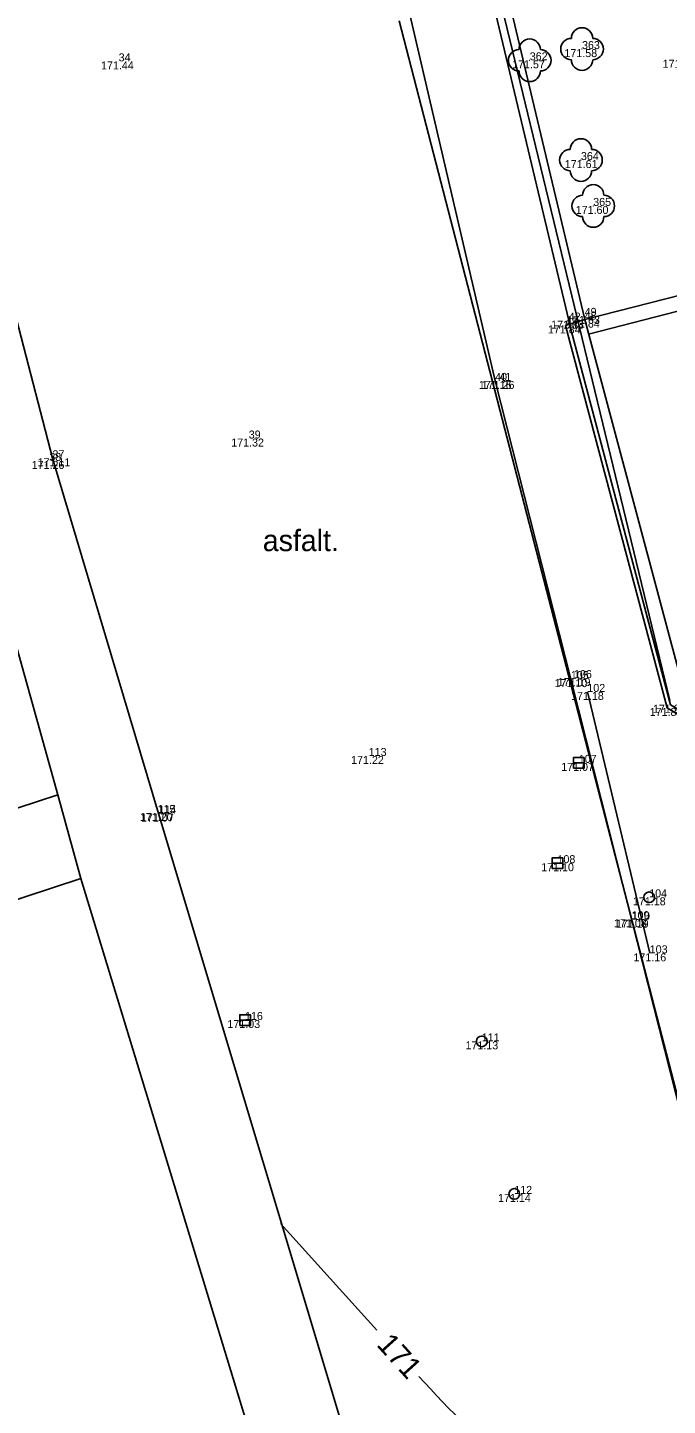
# Model space of a CAD drawing. Extents: x -749392 to -748966, y -963885 to -963538.
# Drawn here: x -749236.19 to -749224.19, y -963704.92 to -963679.09 of the extents above; entities that cross this region are included whole.
import ezdxf

# ---------------------------------------------------------------- set-up
doc = ezdxf.new("R2010")
doc.units = 0
for name, color, linetype in [('_Body výšky', 7, 'Continuous'), ('_Body čísla', 7, 'Continuous'), ('_KM hranice parcel', 7, 'Continuous'), ('_KM vnitřní kresba', 7, 'Continuous'), ('_Kresba', 7, 'Continuous'), ('Vrstevnice', 7, 'Continuous')]:
    doc.layers.add(name, color=color, linetype=linetype)

msp = doc.modelspace()

# ---------------------------------------------------------------- linework, layer by layer
at = {"layer": '_Body čísla'}
for p, q in [((-749225.79, -963679.49), (-749225.79, -963679.49)), ((-749234.48, -963679.72), (-749234.48, -963679.72)), ((-749226.77, -963679.7), (-749226.77, -963679.7)), ((-749225.81, -963681.57), (-749225.81, -963681.57)), ((-749225.58, -963682.43), (-749225.58, -963682.43)), ((-749225.74, -963684.49), (-749225.74, -963684.49)), ((-749226.1, -963684.67), (-749226.1, -963684.67)), ((-749226.04, -963684.58), (-749226.04, -963684.58)), ((-749225.74, -963684.56), (-749225.74, -963684.56)), ((-749227.42, -963685.71), (-749227.42, -963685.71)), ((-749227.34, -963685.71), (-749227.34, -963685.71)), ((-749232.04, -963686.79), (-749232.04, -963686.79)), ((-749235.78, -963687.21), (-749235.78, -963687.21)), ((-749235.72, -963687.16), (-749235.72, -963687.16)), ((-749226, -963691.3), (-749226, -963691.3)), ((-749225.94, -963691.28), (-749225.94, -963691.28)), ((-749225.69, -963691.54), (-749225.69, -963691.54)), ((-749224.19, -963691.84), (-749224.19, -963691.84)), ((-749229.79, -963692.74), (-749229.79, -963692.74)), ((-749225.85, -963692.87), (-749225.85, -963692.87)), ((-749233.75, -963693.81), (-749233.75, -963693.81)), ((-749233.73, -963693.82), (-749233.73, -963693.82)), ((-749226.25, -963694.75), (-749226.25, -963694.75)), ((-749224.53, -963695.39), (-749224.53, -963695.39)), ((-749224.86, -963695.8), (-749224.86, -963695.8)), ((-749224.85, -963695.81), (-749224.85, -963695.81)), ((-749224.52, -963696.44), (-749224.52, -963696.44)), ((-749232.11, -963697.69), (-749232.11, -963697.69)), ((-749227.67, -963698.09), (-749227.67, -963698.09)), ((-749227.06, -963700.95), (-749227.06, -963700.95))]:
    msp.add_line(p, q, dxfattribs=at)
at = {"layer": '_KM hranice parcel'}
for p, q in [((-749229.22, -963678.96), (-749222.92, -963703.3)), ((-749238.25, -963684.05), (-749235.62, -963693.47)), ((-749246.57, -963697.02), (-749235.62, -963693.47)), ((-749235.62, -963693.47), (-749235.19, -963695.04)), ((-749231.34, -963707.66), (-749235.19, -963695.04))]:
    msp.add_line(p, q, dxfattribs=at)
at = {"layer": '_KM vnitřní kresba'}
for p, q in [((-749227.34, -963678.51), (-749224.14, -963691.7)), ((-749244.25, -963698.01), (-749235.19, -963695.04))]:
    msp.add_line(p, q, dxfattribs=at)
at = {"layer": '_Kresba'}
for p, q in [((-749225.74, -963684.56), (-749221.1, -963683.37)), ((-749225.67, -963684.834), (-749221.6, -963683.79)), ((-749225.95, -963692.87), (-749225.75, -963692.87)), ((-749226.35, -963694.75), (-749226.15, -963694.75)), ((-749232.21, -963697.69), (-749232.01, -963697.69))]:
    msp.add_line(p, q, dxfattribs=at)
for points in [[(-749224.86, -963695.8), (-749226, -963691.3), (-749227.42, -963685.71), (-749229.02, -963678.84), (-749230.37, -963670.65), (-749232.38, -963656.9), (-749233.81, -963647.95), (-749234.11, -963645.66), (-749234.87, -963640.98), (-749235.33, -963637.99), (-749235.34, -963637.68), (-749233.84, -963637.45), (-749233.66, -963638.02)], [(-749232.344, -963645.034), (-749230.573, -963656.484), (-749228.394, -963670.774), (-749227.175, -963678.512), (-749225.737, -963684.559)], [(-749232.64, -963645.08), (-749230.87, -963656.53), (-749228.69, -963670.82), (-749227.47, -963678.57), (-749226.04, -963684.58)], [(-749241.6, -963658.41), (-749239.69, -963671.39), (-749237.62, -963679.85), (-749235.72, -963687.16), (-749233.73, -963693.82), (-749229.82, -963706.85)], [(-749221.5, -963692.03), (-749222.72, -963692.33), (-749223.86, -963691.58), (-749225.74, -963684.56), (-749226.1, -963684.67), (-749224.19, -963691.84), (-749222.75, -963692.73), (-749221.57, -963692.38), (-749221.26, -963693.64), (-749222.525, -963693.948)], [(-749226.022, -963684.646), (-749226.04, -963684.58)], [(-749222.959, -963692.601), (-749222.97, -963692.47), (-749224.13, -963691.78), (-749226.022, -963684.646)], [(-749224.52, -963696.44), (-749225.69, -963691.54)], [(-749222.67, -963704.44), (-749224.86, -963695.8)]]:
    msp.add_lwpolyline(points, dxfattribs=at)
for points in [[(-749225.95, -963692.97), (-749225.75, -963692.97), (-749225.75, -963692.77), (-749225.95, -963692.77)], [(-749226.35, -963694.85), (-749226.15, -963694.85), (-749226.15, -963694.65), (-749226.35, -963694.65)], [(-749232.21, -963697.79), (-749232.01, -963697.79), (-749232.01, -963697.59), (-749232.21, -963697.59)]]:
    msp.add_lwpolyline(points, close=True, dxfattribs=at)
for centre, radius in [((-749225.79, -963679.49), 0.0002), ((-749226.77, -963679.7), 0.0002), ((-749225.81, -963681.57), 0.0002), ((-749225.58, -963682.43), 0.0002), ((-749224.53, -963695.39), 0.1), ((-749227.67, -963698.09), 0.1), ((-749227.06, -963700.95), 0.1)]:
    msp.add_circle(centre, radius, dxfattribs=at)
for centre, start, end in [((-749225.79, -963679.29), 0, 180), ((-749226.77, -963679.5), 0, 180), ((-749225.99, -963679.49), 90, 270), ((-749225.59, -963679.49), 270, 90), ((-749226.97, -963679.7), 90, 270), ((-749226.57, -963679.7), 270, 90), ((-749226.77, -963679.9), 180, 360), ((-749225.79, -963679.69), 180, 360), ((-749225.81, -963681.37), 0, 180), ((-749226.01, -963681.57), 90, 270), ((-749225.61, -963681.57), 270, 90), ((-749225.81, -963681.77), 180, 360), ((-749225.58, -963682.23), 0, 180), ((-749225.78, -963682.43), 90, 270), ((-749225.38, -963682.43), 270, 90), ((-749225.58, -963682.63), 180, 360)]:
    msp.add_arc(centre, 0.2, start, end, dxfattribs=at)
at = {"layer": 'Vrstevnice'}
msp.add_line((-749231.442, -963701.506), (-749229.64, -963703.501), dxfattribs=at)
msp.add_spline([(-749228.849, -963704.374), (-749226.934, -963706.051), (-749225.717, -963706.552)], degree=3, dxfattribs=at)

# ---------------------------------------------------------------- texts
at = {"layer": '_Body výšky'}
for s, p in [('171.58', (-749226.12, -963679.64)), ('171.44', (-749234.81, -963679.87)), ('171.57', (-749227.1, -963679.85)), ('171.62', (-749224.278, -963679.84)), ('171.61', (-749226.113, -963681.72)), ('171.60', (-749225.908, -963682.58)), ('171.63', (-749226.068, -963684.64)), ('171.84', (-749226.43, -963684.82)), ('171.33', (-749226.368, -963684.73)), ('171.84', (-749226.07, -963684.71)), ('171.16', (-749227.725, -963685.86)), ('171.26', (-749227.67, -963685.86)), ('171.32', (-749232.368, -963686.94)), ('171.26', (-749236.11, -963687.36)), ('171.11', (-749235.999, -963687.31)), ('171.10', (-749226.305, -963691.45)), ('171.19', (-749226.245, -963691.43)), ('171.18', (-749225.995, -963691.69)), ('171.23', (-749224.46, -963691.93)), ('171.85', (-749224.52, -963691.99)), ('171.22', (-749230.12, -963692.89)), ('171.07', (-749226.18, -963693.02)), ('171.20', (-749234.08, -963693.96)), ('171.07', (-749234.06, -963693.97)), ('171.10', (-749226.555, -963694.9)), ('171.18', (-749224.835, -963695.54)), ('171.08', (-749225.19, -963695.95)), ('171.19', (-749225.155, -963695.96)), ('171.16', (-749224.825, -963696.59)), ('171.03', (-749232.44, -963697.84)), ('171.13', (-749227.975, -963698.24)), ('171.14', (-749227.365, -963701.1))]:
    msp.add_text(s, height=0.15, dxfattribs=at).set_placement(p)
at = {"layer": '_Body čísla'}
for s, p in [('363', (-749225.79, -963679.49)), ('34', (-749234.48, -963679.72)), ('362', (-749226.77, -963679.7)), ('364', (-749225.81, -963681.57)), ('365', (-749225.58, -963682.43)), ('43', (-749226.1, -963684.67)), ('42', (-749226.04, -963684.58)), ('49', (-749225.74, -963684.49)), ('48', (-749225.74, -963684.56)), ('40', (-749227.42, -963685.71)), ('41', (-749227.34, -963685.71)), ('39', (-749232.04, -963686.79)), ('38', (-749235.78, -963687.21)), ('37', (-749235.72, -963687.16)), ('105', (-749226, -963691.3)), ('106', (-749225.94, -963691.28)), ('102', (-749225.69, -963691.54)), ('113', (-749229.79, -963692.74)), ('107', (-749225.85, -963692.87)), ('115', (-749233.75, -963693.81)), ('114', (-749233.73, -963693.82)), ('108', (-749226.25, -963694.75)), ('104', (-749224.53, -963695.39)), ('109', (-749224.86, -963695.8)), ('110', (-749224.85, -963695.81)), ('103', (-749224.52, -963696.44)), ('116', (-749232.11, -963697.69)), ('111', (-749227.67, -963698.09)), ('112', (-749227.06, -963700.95))]:
    msp.add_text(s, height=0.15, dxfattribs=at).set_placement(p)
at = {"layer": '_Kresba'}
msp.add_text('asfalt.', height=0.4, dxfattribs=at).set_placement((-749231.776, -963688.901))
at = {"layer": 'Vrstevnice'}
msp.add_text('171', height=0.4, rotation=312.0939, dxfattribs=at).set_placement((-749229.657, -963703.787))

doc.saveas('drawing.dxf')
